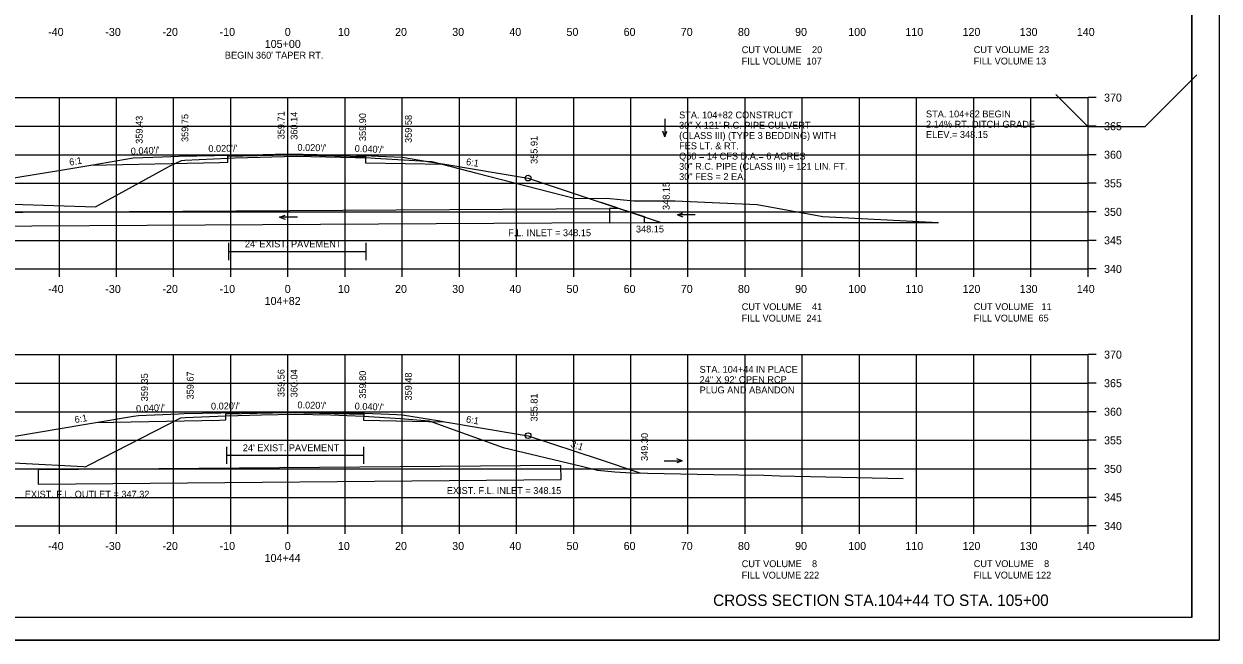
# Model space of a CAD drawing. Extents: x 1374859 to 1376773, y 382242 to 389804.
# Drawn here: x 1376088.4 to 1376297.5, y 382455.1 to 382563 of the extents above; entities that cross this region are included whole.
import ezdxf

# ---------------------------------------------------------------- set-up
doc = ezdxf.new("R2010")
doc.units = 0
for name, color, linetype in [('R_Axis', 7, 'Continuous'), ('R_Axis Annot', 7, 'Continuous'), ('R_Border', 7, 'Continuous'), ('R_Border Notes', 7, 'Continuous'), ('R_Detour Annot', 7, 'Continuous'), ('R_Draft', 7, 'Continuous'), ('R_Erosion', 7, 'Continuous'), ('R_Exist Surface', 7, 'Continuous'), ('R_Fin Surface', 7, 'Continuous'), ('R_Grid', 7, 'Continuous'), ('R_No Plot', 7, 'Continuous'), ('R_Water', 7, 'Continuous'), ('R_Water Annot', 7, 'Continuous'), ('R_Xsect Elev', 7, 'Continuous'), ('R_Xsect Slope', 7, 'Continuous')]:
    doc.layers.add(name, color=color, linetype=linetype)

msp = doc.modelspace()

# ---------------------------------------------------------------- linework, layer by layer
at = {"layer": 'R_Axis'}
for p, q in [((1376274.57, 382520.06), (1376274.57, 382550.06)), ((1376275.97, 382550.06), (1376274.57, 382550.06)), ((1376275.97, 382545.06), (1376274.57, 382545.06)), ((1376275.97, 382540.06), (1376274.57, 382540.06)), ((1376275.97, 382535.06), (1376274.57, 382535.06)), ((1376275.97, 382530.06), (1376274.57, 382530.06)), ((1376275.97, 382525.06), (1376274.57, 382525.06)), ((1375994.57, 382520.06), (1376274.57, 382520.06)), ((1376094.57, 382518.66), (1376094.57, 382520.06)), ((1376104.57, 382518.66), (1376104.57, 382520.06)), ((1376114.57, 382518.66), (1376114.57, 382520.06)), ((1376124.57, 382518.66), (1376124.57, 382520.06)), ((1376134.57, 382518.66), (1376134.57, 382520.06)), ((1376144.57, 382518.66), (1376144.57, 382520.06)), ((1376154.57, 382518.66), (1376154.57, 382520.06)), ((1376164.57, 382518.66), (1376164.57, 382520.06)), ((1376174.57, 382518.66), (1376174.57, 382520.06)), ((1376184.57, 382518.66), (1376184.57, 382520.06)), ((1376194.57, 382518.66), (1376194.57, 382520.06)), ((1376204.57, 382518.66), (1376204.57, 382520.06)), ((1376214.57, 382518.66), (1376214.57, 382520.06)), ((1376224.57, 382518.66), (1376224.57, 382520.06)), ((1376234.57, 382518.66), (1376234.57, 382520.06)), ((1376244.57, 382518.66), (1376244.57, 382520.06)), ((1376254.57, 382518.66), (1376254.57, 382520.06)), ((1376264.57, 382518.66), (1376264.57, 382520.06)), ((1376274.57, 382518.66), (1376274.57, 382520.06)), ((1376275.97, 382520.06), (1376274.57, 382520.06)), ((1376274.57, 382475.06), (1376274.57, 382505.06)), ((1376275.97, 382505.06), (1376274.57, 382505.06)), ((1376275.97, 382500.06), (1376274.57, 382500.06)), ((1376275.97, 382495.06), (1376274.57, 382495.06)), ((1376275.97, 382490.06), (1376274.57, 382490.06)), ((1376275.97, 382485.06), (1376274.57, 382485.06)), ((1376275.97, 382480.06), (1376274.57, 382480.06)), ((1375994.57, 382475.06), (1376274.57, 382475.06)), ((1376094.57, 382473.66), (1376094.57, 382475.06)), ((1376104.57, 382473.66), (1376104.57, 382475.06)), ((1376114.57, 382473.66), (1376114.57, 382475.06)), ((1376124.57, 382473.66), (1376124.57, 382475.06)), ((1376134.57, 382473.66), (1376134.57, 382475.06)), ((1376144.57, 382473.66), (1376144.57, 382475.06)), ((1376154.57, 382473.66), (1376154.57, 382475.06)), ((1376164.57, 382473.66), (1376164.57, 382475.06)), ((1376174.57, 382473.66), (1376174.57, 382475.06)), ((1376184.57, 382473.66), (1376184.57, 382475.06)), ((1376194.57, 382473.66), (1376194.57, 382475.06)), ((1376204.57, 382473.66), (1376204.57, 382475.06)), ((1376214.57, 382473.66), (1376214.57, 382475.06)), ((1376224.57, 382473.66), (1376224.57, 382475.06)), ((1376234.57, 382473.66), (1376234.57, 382475.06)), ((1376244.57, 382473.66), (1376244.57, 382475.06)), ((1376254.57, 382473.66), (1376254.57, 382475.06)), ((1376264.57, 382473.66), (1376264.57, 382475.06)), ((1376274.57, 382473.66), (1376274.57, 382475.06)), ((1376275.97, 382475.06), (1376274.57, 382475.06))]:
    msp.add_line(p, q, dxfattribs=at)
at = {"layer": 'R_Border'}
for q in [(1376292.75, 382664.52), (1375976.57, 382459.06)]:
    msp.add_line((1376292.75, 382459.06), q, dxfattribs=at)
at = {"layer": 'R_Border Notes'}
for points in [[(1376124.17, 382524.62), (1376124.17, 382521.62)], [(1376148.18, 382524.62), (1376148.18, 382521.62)], [(1376124.17, 382523.12), (1376148.18, 382523.12)], [(1376123.8, 382488.94), (1376123.8, 382485.94)], [(1376147.81, 382488.94), (1376147.81, 382485.94)], [(1376123.8, 382487.44), (1376147.81, 382487.44)]]:
    msp.add_lwpolyline(points, dxfattribs=at)
at = {"layer": 'R_Draft'}
for p in [(1376189.31, 382531.73), (1376196.97, 382528.19)]:
    msp.add_line(p, (1376199.86, 382528.21), dxfattribs=at)
msp.add_lwpolyline([(1376069.44, 382529.91), (1376190.81, 382530.65), (1376190.82, 382528.15), (1376069.44, 382527.41)], close=True, dxfattribs=at)
at = {"layer": 'R_Erosion'}
msp.add_lwpolyline([(1376268.92, 382550.63), (1376274.56, 382544.99), (1376284.56, 382544.99), (1376293.59, 382554.02)], dxfattribs=at)
at = {"layer": 'R_Exist Surface'}
for points in [[(1376039.96, 382531.19), (1376067.34, 382531.43), (1376071.67, 382531.42), (1376082.62, 382531.5), (1376100.88, 382530.96), (1376113.85, 382538.06), (1376115.92, 382539.07), (1376116.51, 382539.09), (1376124.08, 382539.47), (1376125.36, 382539.51), (1376136.06, 382539.8), (1376146.32, 382539.6), (1376148.13, 382539.56), (1376149.85, 382539.46), (1376159.74, 382538.88), (1376167.63, 382536.86), (1376184.86, 382532.4), (1376190.34, 382532.46), (1376195.12, 382532.01), (1376202.33, 382531.99), (1376216.67, 382531.33), (1376228.19, 382529.24), (1376248.39, 382528.21)], [(1376066.39, 382486.59), (1376071.92, 382486.61), (1376076.47, 382486.62), (1376098.8, 382485.46), (1376099.17, 382485.43), (1376099.77, 382485.76), (1376115.84, 382494), (1376116.61, 382494.04), (1376123.71, 382494.34), (1376129.97, 382494.5), (1376135.74, 382494.65), (1376142.07, 382494.49), (1376147.81, 382494.31), (1376154.29, 382493.86), (1376159.29, 382493.47), (1376172.24, 382488.78), (1376185.93, 382485.51), (1376188.76, 382484.85), (1376191.74, 382484.52), (1376194.65, 382484.39), (1376209.05, 382484.05), (1376217.85, 382483.96), (1376220.59, 382483.85), (1376242.24, 382483.37)]]:
    msp.add_lwpolyline(points, dxfattribs=at)
at = {"layer": 'R_Fin Surface'}
for points in [[(1376048.48, 382531.27), (1376060.15, 382527.38), (1376072.29, 382531.43), (1376080.97, 382534.32), (1376085.49, 382535.83), (1376094.81, 382537.38), (1376100.06, 382538.25), (1376104.81, 382539.05), (1376107.49, 382539.49), (1376112.61, 382539.7), (1376115.49, 382539.81), (1376127.99, 382540.06), (1376134.59, 382540.2), (1376142.27, 382540.04), (1376146.59, 382539.96), (1376151.71, 382539.75), (1376154.59, 382539.64), (1376159.34, 382538.84), (1376162.02, 382538.4), (1376171.34, 382536.84), (1376176.59, 382535.97), (1376199.86, 382528.21), (1376248.39, 382528.21)], [(1376100.05, 382538.25), (1376122.6, 382538.7), (1376124.08, 382538.73), (1376124.07, 382539.81), (1376134.58, 382540.02), (1376140.09, 382539.92), (1376148.14, 382539.75), (1376148.13, 382538.67), (1376162.02, 382538.4)], [(1376074.05, 382486.62), (1376085.1, 382490.31), (1376086.41, 382490.74), (1376099.23, 382492.88), (1376100.98, 382493.17), (1376107.52, 382494.26), (1376108.41, 382494.41), (1376115.45, 382494.69), (1376116.41, 382494.73), (1376132.53, 382495.05), (1376134.59, 382495.09), (1376145.15, 382494.88), (1376146.59, 382494.85), (1376153.63, 382494.57), (1376154.59, 382494.53), (1376161.12, 382493.44), (1376162.02, 382493.3), (1376174.84, 382491.16), (1376176.59, 382490.87), (1376189, 382486.73), (1376196.12, 382484.36)], [(1376100.98, 382493.17), (1376122.6, 382493.6), (1376123.71, 382493.63), (1376123.7, 382494.71), (1376134.58, 382494.92), (1376140.09, 382494.82), (1376147.83, 382494.66), (1376147.81, 382493.58), (1376162.02, 382493.3)]]:
    msp.add_lwpolyline(points, dxfattribs=at)
at = {"layer": 'R_Grid'}
for p, q in [((1375994.57, 382550.06), (1376274.57, 382550.06)), ((1376094.57, 382520.06), (1376094.57, 382550.06)), ((1376104.57, 382520.06), (1376104.57, 382550.06)), ((1376114.57, 382520.06), (1376114.57, 382550.06)), ((1376124.57, 382520.06), (1376124.57, 382550.06)), ((1376134.57, 382520.06), (1376134.57, 382550.06)), ((1376144.57, 382520.06), (1376144.57, 382550.06)), ((1376154.57, 382520.06), (1376154.57, 382550.06)), ((1376164.57, 382520.06), (1376164.57, 382550.06)), ((1376174.57, 382520.06), (1376174.57, 382550.06)), ((1376184.57, 382520.06), (1376184.57, 382550.06)), ((1376194.57, 382520.06), (1376194.57, 382550.06)), ((1376204.57, 382520.06), (1376204.57, 382550.06)), ((1376214.57, 382520.06), (1376214.57, 382550.06)), ((1376224.57, 382520.06), (1376224.57, 382550.06)), ((1376234.57, 382520.06), (1376234.57, 382550.06)), ((1376244.57, 382520.06), (1376244.57, 382550.06)), ((1376254.57, 382520.06), (1376254.57, 382550.06)), ((1376264.57, 382520.06), (1376264.57, 382550.06)), ((1376274.57, 382520.06), (1376274.57, 382550.06)), ((1375994.57, 382545.06), (1376274.57, 382545.06)), ((1375994.57, 382540.06), (1376274.57, 382540.06)), ((1375994.57, 382535.06), (1376274.57, 382535.06)), ((1375994.57, 382530.06), (1376274.57, 382530.06)), ((1375994.57, 382525.06), (1376274.57, 382525.06)), ((1375994.57, 382520.06), (1376274.57, 382520.06)), ((1375994.57, 382505.06), (1376274.57, 382505.06)), ((1376094.57, 382475.06), (1376094.57, 382505.06)), ((1376104.57, 382475.06), (1376104.57, 382505.06)), ((1376114.57, 382475.06), (1376114.57, 382505.06)), ((1376124.57, 382475.06), (1376124.57, 382505.06)), ((1376134.57, 382475.06), (1376134.57, 382505.06)), ((1376144.57, 382475.06), (1376144.57, 382505.06)), ((1376154.57, 382475.06), (1376154.57, 382505.06)), ((1376164.57, 382475.06), (1376164.57, 382505.06)), ((1376174.57, 382475.06), (1376174.57, 382505.06)), ((1376184.57, 382475.06), (1376184.57, 382505.06)), ((1376194.57, 382475.06), (1376194.57, 382505.06)), ((1376204.57, 382475.06), (1376204.57, 382505.06)), ((1376214.57, 382475.06), (1376214.57, 382505.06)), ((1376224.57, 382475.06), (1376224.57, 382505.06)), ((1376234.57, 382475.06), (1376234.57, 382505.06)), ((1376244.57, 382475.06), (1376244.57, 382505.06)), ((1376254.57, 382475.06), (1376254.57, 382505.06)), ((1376264.57, 382475.06), (1376264.57, 382505.06)), ((1376274.57, 382475.06), (1376274.57, 382505.06)), ((1375994.57, 382500.06), (1376274.57, 382500.06)), ((1375994.57, 382495.06), (1376274.57, 382495.06)), ((1375994.57, 382490.06), (1376274.57, 382490.06)), ((1375994.57, 382485.06), (1376274.57, 382485.06)), ((1375994.57, 382480.06), (1376274.57, 382480.06)), ((1375994.57, 382475.06), (1376274.57, 382475.06))]:
    msp.add_line(p, q, dxfattribs=at)
at = {"layer": 'R_No Plot'}
msp.add_line((1375964.17, 382455.08), (1376297.5, 382455.08), dxfattribs=at)
for points in [[(1375964.16, 382668.41), (1376297.5, 382668.41), (1376297.5, 382455.08), (1375964.16, 382455.08)], [(1376210.49, 382664.52), (1376210.49, 382654.64), (1376246.22, 382654.64), (1376246.22, 382651.72), (1376269.42, 382651.72), (1376269.42, 382627.39), (1376292.75, 382627.39), (1376292.75, 382459.06), (1375976.57, 382459.06), (1375976.57, 382664.52)]]:
    msp.add_lwpolyline(points, close=True, dxfattribs=at)
for centre in [(1376176.59, 382535.97), (1376176.59, 382490.87)]:
    msp.add_circle(centre, 0.5, dxfattribs=at)
at = {"layer": 'R_Water'}
for p, q in [((1376182.34, 382485.64), (1376090.87, 382484.91)), ((1376090.87, 382484.91), (1376090.89, 382482.38)), ((1376182.36, 382483.21), (1376182.34, 382485.64)), ((1376090.89, 382482.38), (1376182.36, 382483.21))]:
    msp.add_line(p, q, dxfattribs=at)
msp.add_lwpolyline([(1376190.81, 382530.65), (1376190.82, 382528.15), (1376196.97, 382528.19), (1376196.96, 382529.19), (1376192.45, 382530.66)], close=True, dxfattribs=at)
at = {"layer": 'R_Water Annot'}
for p, q in [((1376200.51, 382546.35), (1376200.51, 382543.21)), ((1376200.51, 382543.21), (1376200.16, 382544.17)), ((1376200.51, 382543.21), (1376200.86, 382544.17)), ((1376133.09, 382529.13), (1376134.06, 382529.48)), ((1376136.24, 382529.13), (1376133.09, 382529.13)), ((1376133.09, 382529.13), (1376134.06, 382528.78)), ((1376202.71, 382529.54), (1376203.67, 382529.89)), ((1376205.85, 382529.54), (1376202.71, 382529.54)), ((1376202.71, 382529.54), (1376203.67, 382529.19)), ((1376200.43, 382486.46), (1376203.57, 382486.46)), ((1376203.57, 382486.46), (1376202.61, 382486.81)), ((1376203.57, 382486.46), (1376202.61, 382486.11))]:
    msp.add_line(p, q, dxfattribs=at)

# ---------------------------------------------------------------- texts
at = {"layer": 'R_Axis Annot'}
for s, height, p in [('-40', 1.4, (1376092.61, 382560.86)), ('-30', 1.4, (1376102.61, 382560.86)), ('-20', 1.4, (1376112.61, 382560.86)), ('-10', 1.4, (1376122.61, 382560.86)), ('0', 1.4, (1376134.01, 382560.86)), ('10', 1.4, (1376143.31, 382560.86)), ('20', 1.4, (1376153.31, 382560.86)), ('30', 1.4, (1376163.31, 382560.86)), ('40', 1.4, (1376173.31, 382560.86)), ('50', 1.4, (1376183.31, 382560.86)), ('60', 1.4, (1376193.31, 382560.86)), ('70', 1.4, (1376203.31, 382560.86)), ('80', 1.4, (1376213.31, 382560.86)), ('90', 1.4, (1376223.31, 382560.86)), ('100', 1.4, (1376232.61, 382560.86)), ('110', 1.4, (1376242.61, 382560.86)), ('120', 1.4, (1376252.61, 382560.86)), ('130', 1.4, (1376262.61, 382560.86)), ('140', 1.4, (1376272.61, 382560.86)), ('105+00', 1.4, (1376130.51, 382558.76)), ('CUT VOLUME    20', 1.2, (1376213.97, 382557.85)), ('CUT VOLUME  23', 1.2, (1376254.57, 382557.86)), ('FILL VOLUME  107', 1.2, (1376213.97, 382555.85)), ('FILL VOLUME 13', 1.2, (1376254.57, 382555.86)), ('370', 1.4, (1376277.37, 382549.36)), ('365', 1.4, (1376277.37, 382544.36)), ('360', 1.4, (1376277.37, 382539.36)), ('355', 1.4, (1376277.37, 382534.36)), ('350', 1.4, (1376277.37, 382529.36)), ('345', 1.4, (1376277.37, 382524.36)), ('340', 1.4, (1376277.37, 382519.36)), ('-40', 1.4, (1376092.61, 382515.86)), ('-30', 1.4, (1376102.61, 382515.86)), ('-20', 1.4, (1376112.61, 382515.86)), ('-10', 1.4, (1376122.61, 382515.86)), ('0', 1.4, (1376134.01, 382515.86)), ('10', 1.4, (1376143.31, 382515.86)), ('20', 1.4, (1376153.31, 382515.86)), ('30', 1.4, (1376163.31, 382515.86)), ('40', 1.4, (1376173.31, 382515.86)), ('50', 1.4, (1376183.31, 382515.86)), ('60', 1.4, (1376193.31, 382515.86)), ('70', 1.4, (1376203.31, 382515.86)), ('80', 1.4, (1376213.31, 382515.86)), ('90', 1.4, (1376223.31, 382515.86)), ('100', 1.4, (1376232.61, 382515.86)), ('110', 1.4, (1376242.61, 382515.86)), ('120', 1.4, (1376252.61, 382515.86)), ('130', 1.4, (1376262.61, 382515.86)), ('140', 1.4, (1376272.61, 382515.86)), ('104+82', 1.4, (1376130.49, 382513.76)), ('CUT VOLUME    41', 1.2, (1376213.97, 382512.85)), ('CUT VOLUME   11', 1.2, (1376254.57, 382512.86)), ('FILL VOLUME  241', 1.2, (1376213.97, 382510.85)), ('FILL VOLUME  65', 1.2, (1376254.57, 382510.86)), ('370', 1.4, (1376277.37, 382504.36)), ('365', 1.4, (1376277.37, 382499.36)), ('360', 1.4, (1376277.37, 382494.36)), ('355', 1.4, (1376277.37, 382489.36)), ('350', 1.4, (1376277.37, 382484.36)), ('345', 1.4, (1376277.37, 382479.36)), ('340', 1.4, (1376277.37, 382474.36)), ('-40', 1.4, (1376092.61, 382470.86)), ('-30', 1.4, (1376102.61, 382470.86)), ('-20', 1.4, (1376112.61, 382470.86)), ('-10', 1.4, (1376122.61, 382470.86)), ('0', 1.4, (1376134.01, 382470.86)), ('10', 1.4, (1376143.31, 382470.86)), ('20', 1.4, (1376153.31, 382470.86)), ('30', 1.4, (1376163.31, 382470.86)), ('40', 1.4, (1376173.31, 382470.86)), ('50', 1.4, (1376183.31, 382470.86)), ('60', 1.4, (1376193.31, 382470.86)), ('70', 1.4, (1376203.31, 382470.86)), ('80', 1.4, (1376213.31, 382470.86)), ('90', 1.4, (1376223.31, 382470.86)), ('100', 1.4, (1376232.61, 382470.86)), ('110', 1.4, (1376242.61, 382470.86)), ('120', 1.4, (1376252.61, 382470.86)), ('130', 1.4, (1376262.61, 382470.86)), ('140', 1.4, (1376272.61, 382470.86)), ('104+44', 1.4, (1376130.49, 382468.76)), ('CUT VOLUME    8', 1.2, (1376213.97, 382467.85)), ('CUT VOLUME    8', 1.2, (1376254.57, 382467.86)), ('FILL VOLUME 222', 1.2, (1376213.97, 382465.85)), ('FILL VOLUME 122', 1.2, (1376254.57, 382465.86))]:
    msp.add_text(s, height=height, dxfattribs=at).set_placement(p)
at = {"layer": 'R_Border Notes'}
for p in [(1376127.04, 382523.84), (1376126.67, 382488.15)]:
    msp.add_text("24' EXIST. PAVEMENT", height=1.2, rotation=0, dxfattribs=at).set_placement(p)
at = {"layer": 'R_Detour Annot'}
for s, p in [("BEGIN 360' TAPER RT.", (1376123.53, 382556.89)), ('STA. 104+82 BEGIN', (1376246.22, 382546.6)), ('2.14% RT. DITCH GRADE', (1376246.22, 382544.8)), ('ELEV.= 348.15', (1376246.22, 382543))]:
    msp.add_text(s, height=1.2, dxfattribs=at).set_placement(p)
at = {"layer": 'R_Draft'}
msp.add_text('CROSS SECTION STA.104+44 TO STA. 105+00', height=2, dxfattribs=at).set_placement((1376208.97, 382461.06))
at = {"layer": 'R_Water'}
for s, p in [('F.L. INLET = 348.15', (1376173.11, 382525.8)), ('EXIST. F.L. OUTLET = 347.32', (1376088.52, 382480.02)), ('EXIST. F.L. INLET = 348.15', (1376162.37, 382480.66))]:
    msp.add_text(s, height=1.2, dxfattribs=at).set_placement(p)
at = {"layer": 'R_Water Annot'}
for s, p in [('STA. 104+82 CONSTRUCT', (1376203.02, 382546.42)), ('30" X 121\' R.C. PIPE CULVERT', (1376203.02, 382544.62)), ('(CLASS III) (TYPE 3 BEDDING) WITH', (1376203.02, 382542.82)), ('FES LT. & RT.', (1376203.02, 382541.02)), ('30" R.C. PIPE (CLASS III) = 121 LIN. FT.', (1376203.02, 382537.42)), ('Q50 = 14 CFS D.A.= 6 ACRES', (1376203.02, 382539.22)), ('30" FES = 2 EA.', (1376203.02, 382535.62)), ('STA. 104+44 IN PLACE', (1376206.61, 382501.88)), ('24" X 92\' OPEN RCP', (1376206.61, 382500.08)), ('PLUG AND ABANDON', (1376206.61, 382498.28))]:
    msp.add_text(s, height=1.2, dxfattribs=at).set_placement(p)
at = {"layer": 'R_Xsect Elev'}
for s, p in [('359.75', (1376117.15, 382542.29)), ('359.71', (1376133.97, 382542.76)), ('360.14', (1376136.24, 382542.68)), ('359.90', (1376148.24, 382542.44)), ('359.58', (1376156.24, 382542.12)), ('359.43', (1376109.15, 382541.97)), ('355.91', (1376178.24, 382538.45)), ('348.15', (1376201.36, 382530.38)), ('359.35', (1376110.07, 382496.89)), ('359.67', (1376118.07, 382497.21)), ('359.56', (1376133.97, 382497.62)), ('360.04', (1376136.24, 382497.58)), ('359.80', (1376148.24, 382497.34)), ('359.48', (1376156.24, 382497.02)), ('355.81', (1376178.24, 382493.35)), ('349.30', (1376197.56, 382486.44))]:
    msp.add_text(s, height=1.2, rotation=90, dxfattribs=at).set_placement(p)
msp.add_text('348.15', height=1.2, dxfattribs=at).set_placement((1376195.46, 382526.45))
at = {"layer": 'R_Xsect Slope'}
for s, rotation, p in [("0.040'/'", 2.2906, (1376107.09, 382540.08)), ("0.020'/'", 1.1458, (1376120.65, 382540.52)), ("0.020'/'", 358.8542, (1376136.22, 382540.76)), ("0.040'/'", 357.7094, (1376146.23, 382540.57)), ('6:1', 9.4642, (1376096.41, 382538.15)), ('6:1', 350.5358, (1376165.67, 382538.29)), ("0.020'/'", 1.1458, (1376121.11, 382495.42)), ("0.020'/'", 358.8542, (1376136.22, 382495.66)), ("0.040'/'", 2.2906, (1376108.01, 382495)), ("0.040'/'", 357.7094, (1376146.23, 382495.47)), ('6:1', 9.4642, (1376097.33, 382493.07)), ('6:1', 350.5358, (1376165.67, 382493.19)), ('3:1', 341.5651, (1376183.91, 382488.95))]:
    msp.add_text(s, height=1.2, rotation=rotation, dxfattribs=at).set_placement(p)

doc.saveas('drawing.dxf')
